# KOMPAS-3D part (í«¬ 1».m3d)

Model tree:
1. Эскиз:1
2. Операция выдавливания:1
     Расстояние 1 = 3
3. Эскиз:2
4. Операция выдавливания:2
     Расстояние 1 = 78
5. Эскиз:3
6. Операция выдавливания:3
     Расстояние 1 = 3
7. Эскиз:4
8. Операция выдавливания:4
     Расстояние 1 = 4
9. Эскиз:5
10. Операция выдавливания:5
     Расстояние 1 = 4
11. Эскиз:6
12. Вырезать элемент выдавливания:1
     Расстояние 1 = 18.7
